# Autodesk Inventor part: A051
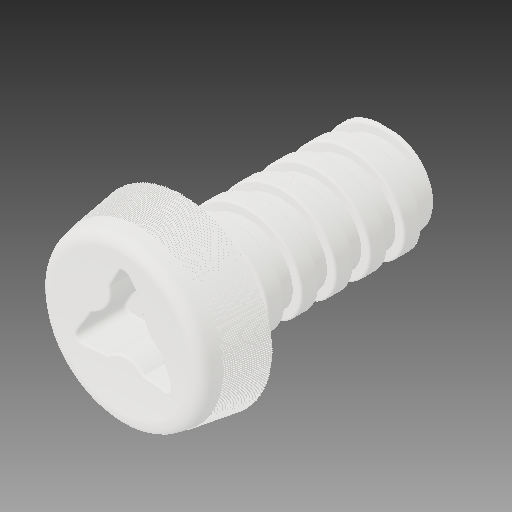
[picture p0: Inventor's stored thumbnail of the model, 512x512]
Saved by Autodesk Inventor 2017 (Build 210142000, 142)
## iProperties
Part Number: A051
Material: Générique
Document SubType Name: Modeling
Designer: ficho
Density: 1 g/cm^3
Appearance: Par défaut
Author: ficho
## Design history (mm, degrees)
feature "Solid1"
node "Solide1"
